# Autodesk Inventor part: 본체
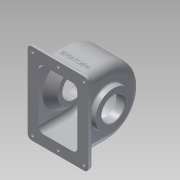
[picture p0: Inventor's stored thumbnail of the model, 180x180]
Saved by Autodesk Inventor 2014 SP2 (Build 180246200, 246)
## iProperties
Created: 2015-09
Part Number: 본체
Material: 알루미늄 6061
Document SubType Name: Modeling
Designer: 201-24
Density: 2.71 g/cm^3
Appearance: 알루미늄 - 평지
Mass: 722.104 g
Surface Area: 895.877 cm^2
Volume: 266.459 cm^3
Author: 201-24
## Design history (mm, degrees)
sketch "스케치1"
  geometry: L1 (-52, -70)-(52, -70); L2 (52, -70)-(52, 70); L3 (52, 70)-(-52, 70); L4 (-52, 70)-(-52, -70); L5 (-52, -70)-(52, 70); L6 (52, -70)-(-52, 70); 1 further point
  constraints: 12 end point, 2 midpoint, 2 parallel, 1 horizontal, 1 perpendicular
  dimensions: "d0" = 104 distance of L2.end L3.end; "d1" = 140 distance of L1.end L2.end
extrude "돌출1" new body sketch "스케치1" distance "d2" = 7; taper "d3" = 0 deg
sketch "스케치3"
  geometry: L1 (-29.846, 0)-(179.075, 0) reference; L2 (7, 70)-(7, -70) reference; L3 (47, 57)-(7, 57); L4 (47, -57)-(7, -57); A1 r 57 centre (47, 0) between (7, 40.608) and (7, -40.608); A2 r 57 centre (47, 0) between (47, 57) and (7, 40.608); A3 r 57 centre (47, 0) between (7, -40.608) and (47, -57); A4 r 57 centre (47, 0) between (47, -57) and (47, 57); 1 further point
  constraints: 9 point on circle, 6 tangent, 5 point on line, 4 centre point, 4 end point, 2 perpendicular
  dimensions: "d4" = 114 diameter of A1; "d5" = 40 distance from line of L2 A1.centre
extrude "돌출2" join sketch "스케치3" stored distance "d6" = 77; taper "d7" = 0 deg
fillet "모깎기1" dims "d8" = 14
sketch "스케치4"
  geometry: L1 (47, -57)-(7, -57) reference; L2 (7, 57)-(47, 57) reference; L3 (7, 51)-(47, 51); L4 (47, -51)-(7, -51); L5 (0, -70)-(0, 70) reference; L6 (7, 51)-(0, 51); L7 (7, -51)-(0, -51); A1 r 57 centre (47, 0) between (47, -57) and (47, 57) reference; A2 r 51 centre (47, 0) between (47, -51) and (47, 51); 1 further point
  constraints: 8 end point, 2 perpendicular, 2 point on circle, 2 point on line, 1 centre point, 2 other
  dimensions: "d9" = 6 radial gap between concentric circles of A1 A2
extrude "돌출3" cut sketch "스케치4" stored distance "d10" = 67; taper "d11" = 0 deg
fillet "모깎기2" dims "d12" = 9
fillet "모깎기3" dims "d13" = 7
sketch "스케치5"
  geometry: C1 r 31 at (0, 47); A1 r 43 centre (0, 47) between (43, 47) and (-43, 47) reference; 1 further point
  constraints: 1 centre point, 1 concentric
  dimensions: "d14" = 62 diameter of C1
extrude "돌출4" join sketch "스케치5" distance "d15" = 10; taper "d16" = 0 deg
sketch "스케치6"
  geometry: C1 r 28 at (0, 47); A1 r 42 centre (0, 47) between (42, 47) and (-42, 47) reference; 1 further point
  constraints: 1 centre point, 1 concentric
  dimensions: "d17" = 56 diameter of C1
extrude "돌출5" join sketch "스케치6" distance "d18" = 14; taper "d19" = 0 deg
chamfer "모따기2" distance "d23" = 14; stored, may be unused: second distance "d24" = 2, angle "d25" = 40 deg
sketch "스케치8"
  geometry: L1 (-19.5, 75)-(-33.5, 86.747) reference; L2 (-19.5, 19)-(-33.5, 7.253) reference; L3 (-19.5, 19)-(-19.5, 75) reference; L4 (-38.5, 47)-(-38.5, 90) reference; L5 (-38.5, 7)-(-38.5, 47) reference; L6 (-38.5, 84.416)-(-24.5, 72.668); L7 (-24.5, 72.668)-(-24.5, 47); L8 (-24.5, 21.332)-(-38.5, 9.584); L9 (-19.5, 47)-(-38.5, 47); L10 (-24.5, 47)-(-24.5, 21.332); L11 (-38.5, 47)-(-38.5, 84.416); 1 further point
  constraints: 12 end point, 3 point on line, 2 perpendicular, 1 midpoint, 1 parallel
  dimensions: "d26" = 5 distance between parallel lines of L1 L6; "d27" = 5 distance between parallel lines of L2 L8; "d28" = 5 distance between parallel lines of L3 L7
revolve "회전1" sketch "스케치8" stored, may be unused: angle "d29" = 90 deg
node "작업 평면1"
sketch "스케치10"
  geometry: C1 r 33 at (0, 47); C2 r 25.668 at (0, 47) reference; 1 further point
  constraints: 1 centre point, 1 concentric
  dimensions: "d31" = 66 diameter of C1
extrude "돌출6" join sketch "스케치10" stored distance "d32" = 14; taper "d33" = 0 deg
hole "구멍1" diameter "d36" = 40; stored, may be unused: countersink angle "d40" = 90 deg, drill point angle "d42" = 0 deg; dims "d37" = 6, "d38" = 4, "d39" = 2, "d41" = 8, "d43" = 10, "d44" = 10
sketch "스케치11"
  geometry: C1 r 20 at (0, 0) reference; 2 further points
  constraints: 1 vertical alignment
  dimensions: "d45" = 28 distance of C1.centre point (0, 28)
hole "구멍2" sketch "스케치11" at (0, 28) diameter "d46" = 2.459; stored, may be unused: countersink angle "d50" = 90 deg, drill point angle "d52" = 118 deg; dims "d47" = 7, "d48" = 4, "d49" = 2, "d51" = 9
sketch "스케치12"
  geometry: C1 r 20 at (0, 0) reference; 2 further points
  constraints: 1 vertical alignment
  dimensions: "d56" = 24 distance of C1.centre point (0, 24)
hole "구멍3" sketch "스케치12" at (0, 24) diameter "d57" = 2.459; stored, may be unused: countersink angle "d61" = 90 deg, drill point angle "d63" = 118 deg; dims "d58" = 6, "d59" = 4, "d60" = 2, "d62" = 8
node "작업 평면2"
sketch "스케치16"
  geometry: L1 (104, 0)-(110, 0); L2 (110, 0)-(110, 6); L3 (110, 6)-(103.551, 7.137); A1 r 57 centre (47, 0) between (47, -57) and (47, 57) reference; 1 further point
  constraints: 6 end point, 2 point on circle, 1 horizontal, 1 perpendicular
  dimensions: "d78" = 6 distance of L1.start L1.end; "d79" = 10 deg angle of L1 L3; "d80" = 6 distance of L1.end L2.end
revolve "회전2" sketch "스케치16" stored, may be unused: angle "d81" = 90 deg
fillet "모깎기5" dims "d82" = 3
hole "구멍4" diameter "d85" = 4.459; stored, may be unused: countersink angle "d89" = 90 deg, drill point angle "d91" = 0 deg; dims "d86" = 20, "d87" = 4, "d88" = 2, "d90" = 20, "d111" = 10, "d112" = 10
sketch "스케치17"
  geometry: L1 (44, -62)-(-44, -62); L2 (-44, -62)-(-44, 62); L3 (-44, 62)-(44, 62); L4 (44, 62)-(44, -62); L5 (44, -62)-(-44, 62); L6 (-44, -62)-(44, 62); 9 further points
  constraints: 12 end point, 5 coincident, 5 midpoint, 2 parallel, 1 horizontal, 1 perpendicular
  dimensions: "d92" = 88 distance of L2.end L3.end; "d93" = 124 distance of L3.end L1.start
hole "구멍5" sketch "스케치17" at (-44, 62), (-44, -62), (44, -62), (44, 62), (0, -62), (0, 62) diameter "d94" = 5; stored, may be unused: countersink angle "d98" = 90 deg, drill point angle "d100" = 118 deg; dims "d95" = 5, "d96" = 4, "d97" = 2, "d99" = 8
fillet "모깎기6" dims "d101" = 3
fillet "모깎기7" dims "d102" = 1
chamfer "모따기4" distance "d103" = 1; stored, may be unused: second distance "d104" = 2, angle "d105" = 10 deg
sketch "스케치18"
  geometry: L1 (-20.5, -47)-(69.5, -47) reference; 3 further points
  constraints: 1 midpoint, 1 vertical alignment, 1 other
  dimensions: "d106" = 30 distance from line of L1 point (24.5, -17)
feature "엠보싱1" sketch "스케치18" dims "d0" = 104, "d1" = 140, "d107" = 0.5, "d108" = 0
fillet "모깎기8" dims "d109" = 3
fillet "모깎기9" dims "d110" = 3
node "솔리드1"
pattern_circular "원형 패턴1" dims angle "d54" = 360 deg
pattern_circular "원형 패턴2" dims angle "d65" = 360 deg
other parameters: "d30" = -3
